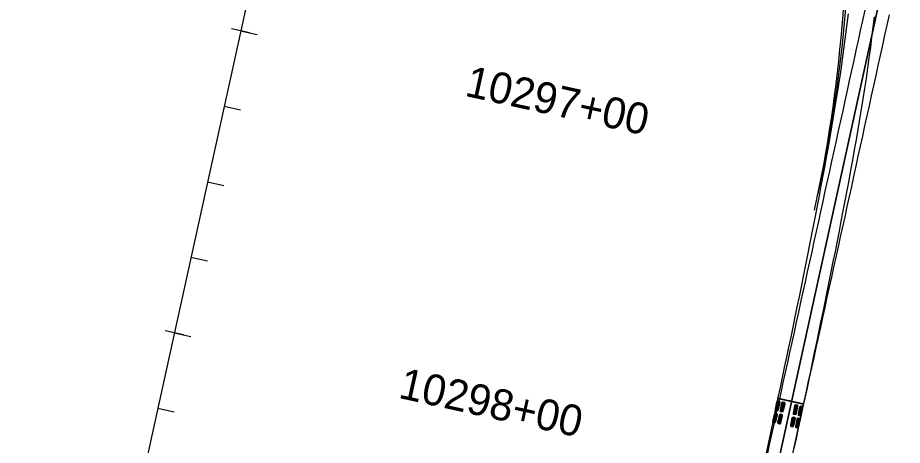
# Model space of a CAD drawing. Extents: x -69 to 14108008, y -6 to 8640172.
# Drawn here: x 14107547.9 to 14107834.1, y 8639162.5 to 8639300.8 of the extents above; entities that cross this region are included whole.
import ezdxf

# ---------------------------------------------------------------- set-up
doc = ezdxf.new("R2010")
doc.units = 0
for name, color, linetype in [('Alignment', 7, 'Continuous'), ('AutoTurn', 7, 'Continuous'), ('Draft_DNC', 7, 'Continuous'), ('TextAlignmentLrg', 7, 'Continuous'), ('TextAlignmentSml', 7, 'Continuous')]:
    doc.layers.add(name, color=color, linetype=linetype)

msp = doc.modelspace()

# ---------------------------------------------------------------- linework, layer by layer
at = {"layer": 'Alignment'}
msp.add_line((14107732.61, 8639808.61), (14107547.95, 8638968.47), dxfattribs=at)
msp.add_arc((14107367.26, 8639340.1), 450, 347.6096, 1.939, dxfattribs=at)
at = {"layer": 'AutoTurn'}
for p, q in [((14107783.36, 8639108.95), (14107834.09, 8639339.91)), ((14107834.09, 8639339.91), (14107783.36, 8639108.95)), ((14107793.79, 8639177.65), (14107802.1, 8639175.87)), ((14107793.18, 8639173.68), (14107793.87, 8639176.91)), ((14107793.4, 8639173.63), (14107794.09, 8639176.86)), ((14107793.63, 8639173.58), (14107794.31, 8639176.81)), ((14107794.79, 8639173.33), (14107795.48, 8639176.56)), ((14107795.01, 8639173.29), (14107795.7, 8639176.51)), ((14107795.24, 8639173.24), (14107795.93, 8639176.47)), ((14107797.44, 8639176.94), (14107797.7, 8639176.88)), ((14107798.21, 8639176.77), (14107797.7, 8639176.88)), ((14107797.96, 8639176.83), (14107797.95, 8639176.76)), ((14107798.22, 8639176.77), (14107798.48, 8639176.72)), ((14107798.98, 8639172.44), (14107799.67, 8639175.67)), ((14107799.2, 8639172.39), (14107799.89, 8639175.62)), ((14107799.43, 8639172.34), (14107800.12, 8639175.57)), ((14107800.59, 8639172.09), (14107801.28, 8639175.32)), ((14107800.82, 8639172.05), (14107801.51, 8639175.27)), ((14107801.04, 8639172), (14107801.73, 8639175.23)), ((14107792.34, 8639169.77), (14107793.03, 8639172.99)), ((14107792.57, 8639169.72), (14107793.26, 8639172.95)), ((14107792.79, 8639169.67), (14107793.48, 8639172.9)), ((14107793.96, 8639169.42), (14107794.64, 8639172.65)), ((14107794.18, 8639169.37), (14107794.87, 8639172.6)), ((14107794.4, 8639169.33), (14107795.09, 8639172.55)), ((14107798.14, 8639168.53), (14107798.83, 8639171.75)), ((14107798.37, 8639168.48), (14107799.06, 8639171.71)), ((14107798.59, 8639168.43), (14107799.28, 8639171.66)), ((14107799.76, 8639168.18), (14107800.45, 8639171.41)), ((14107799.98, 8639168.14), (14107800.67, 8639171.36)), ((14107800.21, 8639168.09), (14107800.9, 8639171.31))]:
    msp.add_line(p, q, dxfattribs=at)
for points in [[(14107821.93, 8639303.19), (14107821.22, 8639299.95), (14107820.51, 8639296.71), (14107819.79, 8639293.47), (14107819.08, 8639290.22), (14107818.37, 8639286.97), (14107817.65, 8639283.72), (14107816.94, 8639280.47), (14107816.22, 8639277.22), (14107815.51, 8639273.96), (14107814.8, 8639270.71), (14107814.08, 8639267.46), (14107813.37, 8639264.2), (14107812.65, 8639260.95), (14107811.93, 8639257.69), (14107811.22, 8639254.44), (14107810.5, 8639251.18), (14107809.79, 8639247.92), (14107809.07, 8639244.67), (14107808.36, 8639241.41), (14107807.64, 8639238.15), (14107806.93, 8639234.9), (14107806.21, 8639231.64), (14107805.5, 8639228.38), (14107804.78, 8639225.12), (14107804.07, 8639221.87), (14107803.35, 8639218.61), (14107802.63, 8639215.35), (14107801.92, 8639212.1), (14107801.2, 8639208.84), (14107800.49, 8639205.58), (14107799.77, 8639202.32), (14107799.06, 8639199.07), (14107798.34, 8639195.81), (14107797.63, 8639192.55), (14107796.91, 8639189.29), (14107796.19, 8639186.04), (14107795.48, 8639182.78), (14107794.76, 8639179.52), (14107794.05, 8639176.26), (14107793.33, 8639173.01), (14107792.62, 8639169.75), (14107791.9, 8639166.49), (14107791.18, 8639163.23), (14107790.47, 8639159.98)], [(14107816.53, 8639302.04), (14107816.15, 8639298.77), (14107815.75, 8639295.51), (14107815.33, 8639292.24), (14107814.88, 8639288.97), (14107814.42, 8639285.7), (14107813.94, 8639282.43), (14107813.44, 8639279.16), (14107812.93, 8639275.89), (14107812.4, 8639272.62), (14107811.87, 8639269.35), (14107811.31, 8639266.08), (14107810.75, 8639262.81), (14107810.18, 8639259.54), (14107809.59, 8639256.27), (14107809, 8639253), (14107808.4, 8639249.74), (14107807.79, 8639246.47), (14107807.17, 8639243.2), (14107806.55, 8639239.94), (14107805.91, 8639236.67), (14107805.28, 8639233.41), (14107804.64, 8639230.14), (14107803.99, 8639226.88), (14107803.34, 8639223.61), (14107802.68, 8639220.35), (14107802.02, 8639217.08), (14107801.35, 8639213.82), (14107800.69, 8639210.56), (14107800.01, 8639207.3), (14107799.34, 8639204.03), (14107798.66, 8639200.77), (14107797.98, 8639197.51), (14107797.3, 8639194.25), (14107796.61, 8639190.99), (14107795.93, 8639187.73), (14107795.24, 8639184.47), (14107794.55, 8639181.21), (14107793.85, 8639177.95), (14107793.16, 8639174.69), (14107792.88, 8639173.38)], [(14107829.79, 8639301.7), (14107829.07, 8639298.43), (14107828.35, 8639295.16), (14107827.64, 8639291.89), (14107826.92, 8639288.62), (14107826.2, 8639285.35), (14107825.48, 8639282.09), (14107824.77, 8639278.82), (14107824.05, 8639275.56), (14107823.33, 8639272.3), (14107822.62, 8639269.04), (14107821.9, 8639265.78), (14107821.19, 8639262.51), (14107820.47, 8639259.26), (14107819.75, 8639256), (14107819.04, 8639252.74), (14107818.32, 8639249.48), (14107817.61, 8639246.22), (14107816.89, 8639242.96), (14107816.17, 8639239.7), (14107815.46, 8639236.44), (14107814.74, 8639233.19), (14107814.03, 8639229.93), (14107813.31, 8639226.67), (14107812.6, 8639223.41), (14107811.88, 8639220.15), (14107811.16, 8639216.9), (14107810.45, 8639213.64), (14107809.73, 8639210.38), (14107809.02, 8639207.12), (14107808.3, 8639203.87), (14107807.59, 8639200.61), (14107806.87, 8639197.35), (14107806.15, 8639194.09), (14107805.44, 8639190.84), (14107804.72, 8639187.58), (14107804.01, 8639184.32), (14107803.29, 8639181.06), (14107802.58, 8639177.81), (14107801.86, 8639174.55), (14107801.15, 8639171.29), (14107800.43, 8639168.03), (14107799.71, 8639164.77), (14107799, 8639161.52)], [(14107824.97, 8639301.1), (14107824.59, 8639297.77), (14107824.18, 8639294.45), (14107823.75, 8639291.12), (14107823.3, 8639287.81), (14107822.83, 8639284.49), (14107822.35, 8639281.18), (14107821.84, 8639277.87), (14107821.33, 8639274.56), (14107820.79, 8639271.25), (14107820.25, 8639267.95), (14107819.69, 8639264.65), (14107819.12, 8639261.35), (14107818.55, 8639258.06), (14107817.96, 8639254.77), (14107817.36, 8639251.48), (14107816.75, 8639248.19), (14107816.14, 8639244.9), (14107815.52, 8639241.62), (14107814.89, 8639238.33), (14107814.26, 8639235.05), (14107813.62, 8639231.77), (14107812.97, 8639228.49), (14107812.32, 8639225.22), (14107811.67, 8639221.94), (14107811.01, 8639218.67), (14107810.35, 8639215.39), (14107809.68, 8639212.12), (14107809.01, 8639208.85), (14107808.34, 8639205.58), (14107807.66, 8639202.31), (14107806.98, 8639199.04), (14107806.3, 8639195.77), (14107805.62, 8639192.51), (14107804.93, 8639189.24), (14107804.24, 8639185.97), (14107803.55, 8639182.71), (14107802.86, 8639179.44), (14107802.17, 8639176.18), (14107801.47, 8639172.91), (14107801.19, 8639171.61)], [(14107793.83, 8639177.71), (14107793.81, 8639177.71), (14107793.79, 8639177.65), (14107792.61, 8639172.1), (14107782.76, 8639125.95), (14107786.91, 8639125.06), (14107791.07, 8639124.18), (14107800.92, 8639170.33), (14107802.1, 8639175.87), (14107802.12, 8639175.94), (14107802.1, 8639175.95)], [(14107797.72, 8639176.95), (14107797.46, 8639177.01), (14107797.46, 8639177.01), (14107797.44, 8639176.94), (14107797.41, 8639176.95), (14107793.85, 8639177.71), (14107793.85, 8639177.71)], [(14107802.07, 8639175.95), (14107802.07, 8639175.95), (14107798.52, 8639176.71), (14107798.48, 8639176.72), (14107798.49, 8639176.79), (14107798.49, 8639176.79), (14107798.23, 8639176.84)]]:
    msp.add_lwpolyline(points, dxfattribs=at)
for points in [[(14107793.68, 8639173.57), (14107793.12, 8639173.69), (14107793.05, 8639174.18), (14107793.55, 8639176.5), (14107793.81, 8639176.92), (14107794.37, 8639176.8), (14107794.44, 8639176.31), (14107793.95, 8639173.99)], [(14107795.29, 8639173.23), (14107794.74, 8639173.35), (14107794.66, 8639173.83), (14107795.16, 8639176.16), (14107795.42, 8639176.57), (14107795.98, 8639176.45), (14107796.06, 8639175.97), (14107795.56, 8639173.64)], [(14107799.48, 8639172.33), (14107798.92, 8639172.45), (14107798.85, 8639172.94), (14107799.35, 8639175.26), (14107799.61, 8639175.68), (14107800.17, 8639175.56), (14107800.24, 8639175.07), (14107799.75, 8639172.75)], [(14107801.1, 8639171.99), (14107800.54, 8639172.11), (14107800.47, 8639172.59), (14107800.96, 8639174.92), (14107801.23, 8639175.33), (14107801.79, 8639175.21), (14107801.86, 8639174.73), (14107801.36, 8639172.4)], [(14107792.85, 8639169.66), (14107792.29, 8639169.78), (14107792.21, 8639170.27), (14107792.71, 8639172.59), (14107792.98, 8639173.01), (14107793.53, 8639172.89), (14107793.61, 8639172.4), (14107793.11, 8639170.07)], [(14107794.46, 8639169.31), (14107793.9, 8639169.43), (14107793.83, 8639169.92), (14107794.32, 8639172.24), (14107794.59, 8639172.66), (14107795.15, 8639172.54), (14107795.22, 8639172.05), (14107794.72, 8639169.73)], [(14107798.65, 8639168.42), (14107798.09, 8639168.54), (14107798.02, 8639169.03), (14107798.51, 8639171.35), (14107798.78, 8639171.77), (14107799.34, 8639171.65), (14107799.41, 8639171.16), (14107798.91, 8639168.84)], [(14107800.26, 8639168.08), (14107799.7, 8639168.19), (14107799.63, 8639168.68), (14107800.13, 8639171.01), (14107800.39, 8639171.42), (14107800.95, 8639171.3), (14107801.02, 8639170.82), (14107800.53, 8639168.49)]]:
    msp.add_lwpolyline(points, close=True, dxfattribs=at)
for centre, radius in [((14107793.85, 8639177.74), 0.0266), ((14107802.09, 8639175.98), 0.0266), ((14107792.88, 8639173.38), 0.0417), ((14107801.19, 8639171.61), 0.0417)]:
    msp.add_circle(centre, radius, dxfattribs=at)
for centre, radius, start, end in [((14107794.25, 8639179.69), 2.02, 257.9529, 258.6366), ((14107797.71, 8639176.92), 0.0354, 82.2444, 254.4299), ((14107797.71, 8639176.92), 0.0352, 258.9272, 77.9276), ((14107798.23, 8639176.81), 0.0352, 77.9781, 256.9785), ((14107798.23, 8639176.81), 0.0353, 261.289, 79.6387), ((14107802.09, 8639175.98), 0.0363, 277.0303, 238.1916)]:
    msp.add_arc(centre, radius, start, end, dxfattribs=at)
at = {"layer": 'Draft_DNC'}
msp.add_arc((14107366.15, 8639335.06), 450, 347.6102, 2.9347, dxfattribs=at)
at = {"layer": 'TextAlignmentLrg'}
for p, q in [((14107620.07, 8639296.58), (14107625.4, 8639295.41)), ((14107598.6, 8639198.91), (14107603.93, 8639197.74))]:
    msp.add_line(p, q, dxfattribs=at)
at = {"layer": 'TextAlignmentSml'}
for p, q in [((14107623.06, 8639295.93), (14107617.08, 8639297.24)), ((14107614.7, 8639272.17), (14107620.03, 8639270.99)), ((14107609.33, 8639247.75), (14107614.67, 8639246.58)), ((14107603.97, 8639223.33), (14107609.3, 8639222.16)), ((14107601.59, 8639198.26), (14107595.61, 8639199.57)), ((14107593.23, 8639174.5), (14107598.56, 8639173.32))]:
    msp.add_line(p, q, dxfattribs=at)

# ---------------------------------------------------------------- texts
for s, p in [('10297+00', (14107692.24, 8639275.59)), ('10298+00', (14107670.77, 8639177.92))]:
    msp.add_text(s, height=10.02, rotation=347.6032, dxfattribs=at).set_placement(p)

doc.saveas('drawing.dxf')
